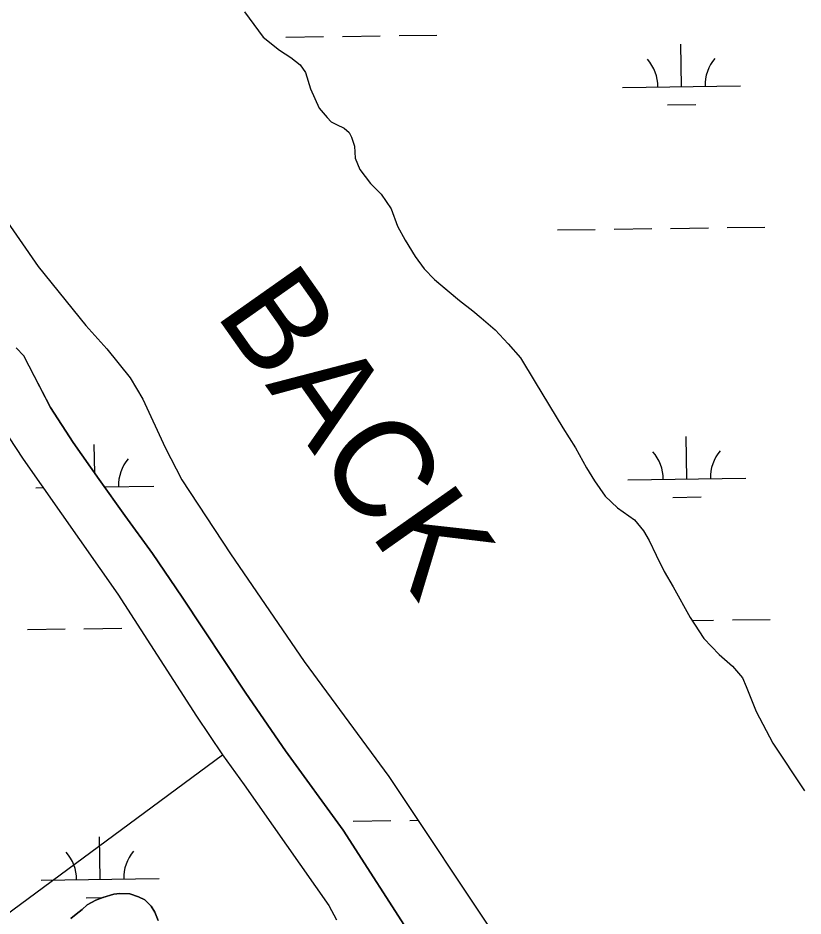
# Model space of a CAD drawing. Extents: x 3753511 to 3791668, y 379550 to 405377.
# Drawn here: x 3781037 to 3781703, y 389999 to 390761 of the extents above; entities that cross this region are included whole.
import ezdxf

# ---------------------------------------------------------------- set-up
doc = ezdxf.new("R2010")
doc.units = 0
for name, color, linetype in [('V-RIVR-IDEN', 7, 'Continuous'), ('V-TOPO-SHOR', 7, 'Continuous'), ('V-WETL-SWMP', 7, 'Continuous')]:
    doc.layers.add(name, color=color, linetype=linetype)

msp = doc.modelspace()

# ---------------------------------------------------------------- linework, layer by layer
at = {"layer": 'V-TOPO-SHOR'}
msp.add_line((3780437.07, 389564.52), (3781210.36, 390135.73), dxfattribs=at)
for points in [[(3780548.3, 391141.71), (3780653.89, 391018.66), (3780721.81, 390944.79), (3780792.08, 390863.69), (3780867.17, 390784.96), (3780895.77, 390754.28), (3780924, 390726.81), (3780937.5, 390711.47), (3780952.16, 390690.92), (3780962.43, 390672.81), (3780974.68, 390651.87), (3780986.58, 390636.55), (3781019.54, 390599.43), (3781054, 390549.87), (3781094.46, 390499.86), (3781112.34, 390480.09), (3781132.17, 390455.48), (3781142.85, 390437.37), (3781161.75, 390396.35), (3781175.95, 390368.99), (3781217.12, 390306.16), (3781279.69, 390215.1), (3781351.43, 390117.57), (3781444.46, 389977.79)], [(3780640.18, 390860.39), (3780762.71, 390730.96), (3780803.23, 390689.18), (3780821.48, 390671.83), (3780850.05, 390651.46), (3780868.71, 390636.84), (3780880.36, 390626.97), (3780891.62, 390616.91), (3780899.38, 390609.61), (3780906.56, 390602.32), (3780911.59, 390596.03), (3780916.81, 390589.34), (3780931.08, 390564.2), (3780939.13, 390544.38), (3780951.47, 390522.19), (3780963.08, 390507.24), (3780986.63, 390469.51), (3781041.49, 390386.56), (3781121.71, 390272.13), (3781188.33, 390168.75), (3781210.36, 390135.73), (3781228.93, 390110.55), (3781300.64, 390008.11), (3781307.19, 389995.93)], [(3781229.05, 390765.73), (3781245.04, 390744.18), (3781258.69, 390733.16), (3781268.34, 390727.02), (3781276.38, 390720.9), (3781280.77, 390714.4), (3781285.1, 390700.62), (3781292.25, 390683.99), (3781299.05, 390676.26), (3781302.66, 390672.59), (3781307.09, 390670.13), (3781313.53, 390667.25), (3781317.95, 390663.58), (3781319.94, 390659.52), (3781322.3, 390651.83), (3781323.03, 390641.72), (3781326.99, 390631.99), (3781335.79, 390620.2), (3781345.01, 390611.23), (3781353.39, 390598.64)], [(3781353.39, 390598.64), (3781358.93, 390584.04), (3781365.31, 390572.27), (3781373.68, 390558.47), (3781381.27, 390547.9), (3781390.09, 390538.93), (3781399.33, 390531.18), (3781411.37, 390520.98), (3781422.61, 390512.41), (3781429.84, 390506.29), (3781441.48, 390496.09), (3781452.7, 390484.28), (3781463.11, 390472.48), (3781475.47, 390451.76), (3781499.01, 390413.18), (3781509.78, 390396.12), (3781518.94, 390379.08), (3781525.72, 390368.11), (3781534.91, 390355.1), (3781545.34, 390345.32), (3781559.81, 390335.1), (3781567.41, 390325.75), (3781572.2, 390317.63), (3781578.16, 390305.05), (3781584.92, 390291.25), (3781592.49, 390278.26), (3781606.83, 390252.28), (3781618.41, 390234.41), (3781631.64, 390220.97), (3781642.87, 390211.18), (3781651.28, 390201.01), (3781654.45, 390193.71), (3781662.77, 390172.63), (3781677.1, 390145.84), (3781703.85, 390105.21)], [(3781035.42, 390481.02), (3781041.93, 390474.21), (3781046.82, 390464.62), (3781064.64, 390430.27), (3781083.9, 390400.68), (3781105.72, 390369.28), (3781127.55, 390338.68), (3781150.96, 390306.47), (3781176.12, 390269.67), (3781230.16, 390188.29), (3781263.78, 390139.29), (3781312.76, 390072.08), (3781372.48, 389979.31)], [(3781091.42, 390004.87), (3781095.79, 390008.58), (3781102.93, 390012.67), (3781108.87, 390014.79), (3781118.17, 390017.68), (3781123.31, 390018.43), (3781131.99, 390017.96), (3781139.08, 390015.54), (3781144.58, 390012.93), (3781150.06, 390007.55), (3781153.18, 390002.4), (3781155.89, 389995.47)], [(3781081.88, 389997.24), (3781086.45, 390000.76), (3781091.42, 390004.87)]]:
    msp.add_lwpolyline(points, dxfattribs=at)
at = {"layer": 'V-WETL-SWMP'}
for p, q in [((3781264.15, 390744.3), (3781296.14, 390744.73)), ((3781312.14, 390744.95), (3781344.14, 390745.38)), ((3781360.14, 390745.6), (3781392.13, 390746.03)), ((3781599.59, 390702.4), (3781599.1, 390738.4)), ((3781549.59, 390701.73), (3781649.58, 390703.08)), ((3781587.8, 390686.81), (3781611.79, 390687.13)), ((3781590.37, 390582.2), (3781622.36, 390582.63)), ((3781638.36, 390582.84), (3781670.36, 390583.28)), ((3781494.38, 390580.9), (3781526.37, 390581.33)), ((3781542.37, 390581.55), (3781574.37, 390581.98)), ((3781604.09, 390369.76), (3781603.6, 390405.75)), ((3781102.07, 390374.54), (3781101.74, 390398.97)), ((3781554.09, 390369.08), (3781654.08, 390370.43)), ((3781052.23, 390362.29), (3781058.44, 390362.38)), ((3781110.15, 390363.08), (3781152.22, 390363.65)), ((3781592.29, 390354.17), (3781616.29, 390354.49)), ((3781608.48, 390249.73), (3781626.86, 390249.98)), ((3781642.86, 390250.2), (3781674.86, 390250.63)), ((3781045.01, 390242.12), (3781077, 390242.55)), ((3781093, 390242.76), (3781125, 390243.2)), ((3781321.14, 390079.66), (3781353.13, 390080.09)), ((3781369.13, 390080.31), (3781376.16, 390080.4)), ((3781106.72, 390030.33), (3781106.23, 390066.32)), ((3781056.73, 390029.65), (3781156.72, 390031)), ((3781094.93, 390014.73), (3781109.31, 390014.93))]:
    msp.add_line(p, q, dxfattribs=at)
for points in [[(3780548.3, 391141.71), (3780653.89, 391018.66), (3780721.81, 390944.79), (3780792.08, 390863.69), (3780867.17, 390784.96), (3780895.77, 390754.28), (3780924, 390726.81), (3780937.5, 390711.47), (3780952.16, 390690.92), (3780962.43, 390672.81), (3780974.68, 390651.88), (3780986.58, 390636.55), (3781019.54, 390599.43), (3781054, 390549.87), (3781094.46, 390499.86), (3781112.33, 390480.09), (3781132.17, 390455.49), (3781142.84, 390437.37), (3781161.75, 390396.35), (3781175.95, 390368.99), (3781217.12, 390306.16), (3781279.69, 390215.1), (3781351.43, 390117.57), (3781444.46, 389977.79)], [(3780640.18, 390860.39), (3780762.71, 390730.96), (3780803.24, 390689.18), (3780821.48, 390671.83), (3780850.05, 390651.46), (3780868.71, 390636.84), (3780880.36, 390626.97), (3780891.62, 390616.91), (3780899.38, 390609.61), (3780906.55, 390602.32), (3780916.81, 390589.34), (3780931.08, 390564.2), (3780939.13, 390544.38), (3780951.47, 390522.19), (3780963.08, 390507.24), (3780986.63, 390469.51), (3781041.49, 390386.56), (3781121.71, 390272.13), (3781188.33, 390168.75), (3781210.36, 390135.73), (3781228.93, 390110.55), (3781300.64, 390008.11), (3781307.19, 389995.93)], [(3781229.05, 390765.73), (3781245.04, 390744.18), (3781258.69, 390733.16), (3781268.34, 390727.02), (3781276.38, 390720.9), (3781280.77, 390714.4), (3781285.1, 390700.62), (3781292.25, 390683.99), (3781299.05, 390676.26), (3781302.66, 390672.59), (3781307.09, 390670.13), (3781313.53, 390667.25)], [(3781313.53, 390667.25), (3781317.95, 390663.58), (3781319.94, 390659.52), (3781322.3, 390651.83), (3781323.02, 390641.72), (3781326.99, 390631.99), (3781335.78, 390620.2), (3781345.01, 390611.23), (3781353.39, 390598.64), (3781358.93, 390584.04), (3781365.31, 390572.27), (3781373.68, 390558.46), (3781381.27, 390547.9), (3781390.09, 390538.93), (3781411.37, 390520.98), (3781422.62, 390512.41), (3781429.84, 390506.29), (3781441.48, 390496.09), (3781452.7, 390484.28), (3781463.11, 390472.48), (3781475.47, 390451.77), (3781499.01, 390413.18), (3781509.78, 390396.12), (3781518.94, 390379.08), (3781525.72, 390368.11), (3781534.91, 390355.1), (3781545.34, 390345.32), (3781559.81, 390335.1), (3781567.41, 390325.75), (3781572.2, 390317.63), (3781578.16, 390305.05), (3781584.92, 390291.26), (3781592.49, 390278.26), (3781606.83, 390252.28), (3781618.41, 390234.41), (3781631.64, 390220.97), (3781642.87, 390211.18), (3781651.28, 390201.01), (3781654.45, 390193.71), (3781662.77, 390172.62), (3781677.1, 390145.84), (3781703.85, 390105.21)], [(3781372.48, 389979.31), (3781312.76, 390072.08), (3781263.78, 390139.29), (3781230.16, 390188.29), (3781176.12, 390269.67), (3781150.96, 390306.47), (3781127.55, 390338.68), (3781105.72, 390369.28), (3781083.9, 390400.68), (3781064.64, 390430.27), (3781041.93, 390474.21), (3781035.42, 390481.02)], [(3781155.89, 389995.47), (3781153.18, 390002.4), (3781150.06, 390007.55), (3781144.58, 390012.93), (3781139.08, 390015.54), (3781131.99, 390017.96), (3781123.31, 390018.43), (3781118.17, 390017.68), (3781108.87, 390014.79), (3781102.93, 390012.67), (3781095.79, 390008.58), (3781091.42, 390004.87), (3781086.45, 390000.76), (3781081.88, 389997.24)]]:
    msp.add_lwpolyline(points, dxfattribs=at)
for centre, start, end in [((3781544.34, 390702.13), 0.00289, 41.54655), ((3781654.82, 390703.62), 140.00289, 181.54655), ((3781548.84, 390369.48), 0.00289, 41.54655), ((3781659.32, 390370.98), 140.00289, 181.54655), ((3781157.45, 390364.19), 140.00289, 181.54655), ((3781051.48, 390030.05), 0.00289, 41.54655), ((3781161.95, 390031.55), 140.00289, 181.54655)]:
    msp.add_arc(centre, 35.25, start, end, dxfattribs=at)

# ---------------------------------------------------------------- texts
at = {"layer": 'V-RIVR-IDEN'}
msp.add_text('BACK', height=83, rotation=305.16641, dxfattribs=at).set_placement((3781203.55, 390510.1))

doc.saveas('drawing.dxf')
